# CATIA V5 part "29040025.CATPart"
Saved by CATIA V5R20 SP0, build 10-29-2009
Part number: 29040025
Definition: NONE
Nomenclature: 29040025
Source: Unknown
Description: 29040025
Bounding box of the stored display mesh (mm): x -12.5 to 44.548, y -34 to 68.548, z -24 to 24
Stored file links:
  C:\Users\Utente\Desktop\IO LAVORO\3D X SITO CF\X SITO\PLASTICA\RF1\29040025.CATPart
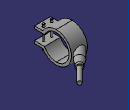
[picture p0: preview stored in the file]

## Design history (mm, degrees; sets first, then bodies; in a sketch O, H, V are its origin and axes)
Body1 "29040025" (main body)
  Solid1: solid without history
